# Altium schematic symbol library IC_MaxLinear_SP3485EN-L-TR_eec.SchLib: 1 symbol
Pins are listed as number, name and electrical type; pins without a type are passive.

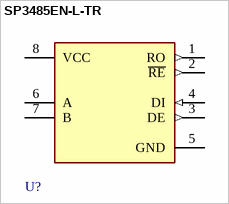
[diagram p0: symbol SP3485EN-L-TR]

## SP3485EN-L-TR
designator U?  (value not drawn)
pins: 1 RO (out), 2 ~{RE} (out), 3 DE (out), 4 DI (in), 5 GND (power), 6 A (hiz), 7 B (hiz), 8 VCC (power)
